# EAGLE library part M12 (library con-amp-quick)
AMP QUICK CONNECTOR
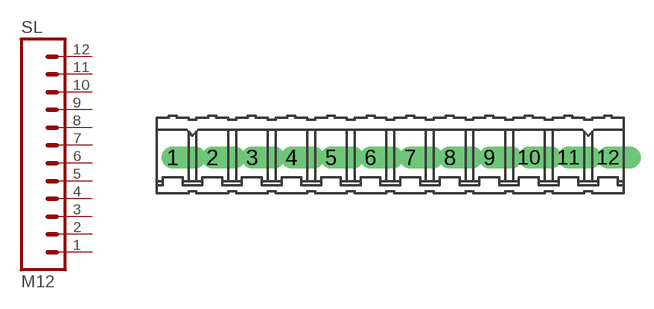
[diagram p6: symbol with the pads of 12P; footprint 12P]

Designator prefix SL

## M12  [12P]
1  1  pas
2  2  pas
3  3  pas
4  4  pas
5  5  pas
6  6  pas
7  7  pas
8  8  pas
9  9  pas
10  10  pas
11  11  pas
12  12  pas

## Footprint 12P (pad centres in mm)
AMP QUICK CONNECTOR
drill 0.914 offset: 1 -13.97,0; 2 -11.43,0; 3 -8.89,0; 4 -6.35,0; 5 -3.81,0; 6 -1.27,0; 7 1.27,0; 8 3.81,0; 9 6.35,0; 10 8.89,0; 11 11.43,0; 12 13.97,0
